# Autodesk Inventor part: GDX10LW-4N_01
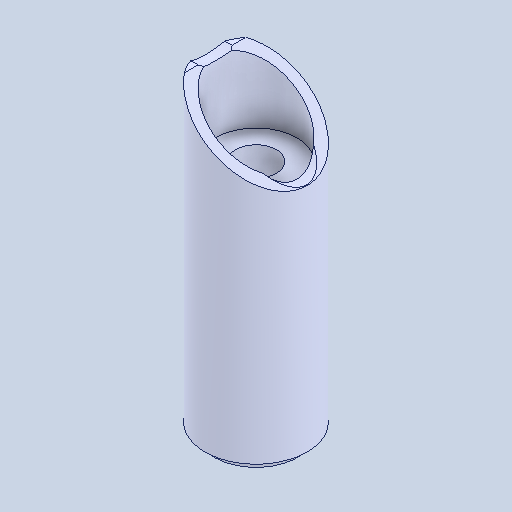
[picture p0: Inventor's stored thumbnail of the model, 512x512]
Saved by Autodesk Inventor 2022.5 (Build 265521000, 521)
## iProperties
Created: 2024-06
Part Number: GDX10LW-4N_01
Material: 一般
Document SubType Name: Modeling
Designer: ImaoCorp
Density: 1 g/cm^3
Appearance: 既定
Author: ImaoCorp
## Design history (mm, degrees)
feature "GDX10LW-4N_01"
node "ソリッド1"
